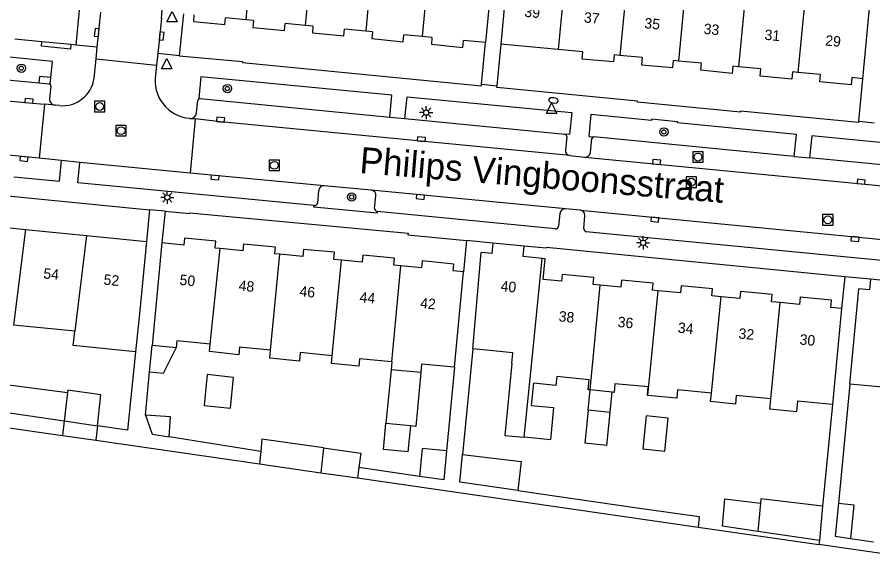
# Model space of a CAD drawing. Extents: x 132998 to 136004, y 396998 to 398512.
# Drawn here: x 133315.3 to 133397.2, y 397209.9 to 397262.2 of the extents above; entities that cross this region are included whole.
import ezdxf

# ---------------------------------------------------------------- set-up
doc = ezdxf.new("R2010")
doc.units = 0
for name, color, linetype in [('gg-afsc-erfafscheiding', 7, 'Continuous'), ('gg-anno-huisnummerreeks BGT', 7, 'Continuous'), ('gg-anno-openbare ruimte label', 7, 'Continuous'), ('gg-bbg-gedigitaliseerde bebouwing', 7, 'Continuous'), ('gg-bbg-gedigitaliseerde bijgebouw', 7, 'Continuous'), ('gg-bbg-hoofdgebouw', 7, 'Continuous'), ('gg-bbg-luifel en loopbrug', 7, 'Continuous'), ('gg-bbg-tussenscheiding', 7, 'Continuous'), ('gg-knt-verharding', 7, 'Continuous'), ('gg-knt-verharding nz', 7, 'Continuous'), ('gt-grn-weggrens', 7, 'Continuous'), ('gt-symb-boom', 7, 'Continuous'), ('gt-symb-brandkraan', 7, 'Continuous'), ('gt-symb-kolk', 7, 'Continuous'), ('gt-symb-lichtmast', 7, 'Continuous'), ('gt-symb-rioolschacht', 7, 'Continuous'), ('gt-symb-waterafsluiter', 7, 'Continuous')]:
    doc.layers.add(name, color=color, linetype=linetype)

# ---------------------------------------------------------------- blocks, each defined once
blk = doc.blocks.new('gt0-RS')
at = {"layer": 'gt-symb-rioolschacht'}
blk.add_lwpolyline([(-0.5, -0.5), (0.5, -0.5), (0.5, 0.5), (-0.5, 0.5)], close=True, dxfattribs=at)
blk.add_circle((0, 0), 0.375, dxfattribs=at)
blk = doc.blocks.new('gt0-KOLK')
at = {"layer": 'gt-symb-kolk'}
blk.add_lwpolyline([(0, 0), (0.375, 0), (0.375, 0.4), (-0.375, 0.4), (-0.375, 0), (0, 0)], dxfattribs=at)
blk = doc.blocks.new('gt0-LMAST')
at = {"layer": 'gt-symb-lichtmast'}
for p, q in [((-0.182, 0.173), (-0.447, 0.438)), ((-0.005, 0.246), (-0.005, 0.621)), ((0.172, 0.173), (0.437, 0.438)), ((-0.255, -0.004), (-0.63, -0.004)), ((-0.182, -0.181), (-0.447, -0.446)), ((-0.005, -0.254), (-0.005, -0.629)), ((0.437, -0.446), (0.172, -0.181)), ((0.245, -0.004), (0.62, -0.004))]:
    blk.add_line(p, q, dxfattribs=at)
blk.add_circle((-0.005, -0.004), 0.25, dxfattribs=at)
blk = doc.blocks.new('gt0-BOOM')
at = {"layer": 'gt-symb-boom'}
for radius in [0.4, 0.2]:
    blk.add_circle((0, 0), radius, dxfattribs=at)
blk = doc.blocks.new('gt0-WAFSL')
at = {"layer": 'gt-symb-waterafsluiter'}
for p, q in [((-0.5, -0.333), (0, 0.667)), ((0, 0.667), (0.5, -0.333)), ((0.5, -0.333), (-0.5, -0.333))]:
    blk.add_line(p, q, dxfattribs=at)
blk = doc.blocks.new('gt0-BR')
at = {"layer": 'gt-symb-brandkraan'}
for centre, radius, start, end in [((-0.244, 0), 0.206, 107.56694, 252.43307), ((0.599, -2.664), 3, 106.89205, 107.56694), ((0, -0.691), 0.938, 73.10799, 106.89205), ((-0.599, -2.664), 3, 72.43309, 73.10799), ((0.244, 0), 0.206, 287.56695, 72.43309), ((0.599, 2.664), 3, 252.43307, 253.10797), ((0, 0.691), 0.938, 253.10797, 286.89206), ((-0.599, 2.664), 3, 286.89206, 287.56695)]:
    blk.add_arc(centre, radius, start, end, dxfattribs=at)

msp = doc.modelspace()

# ---------------------------------------------------------------- linework, layer by layer
at = {"layer": 'gg-afsc-erfafscheiding'}
for p, q in [((133358.937, 397230.482), (133357.969, 397220.358)), ((133327.615, 397224.121), (133328.011, 397228.268)), ((133357.197, 397228.715), (133356.425, 397220.702)), ((133395.041, 397227.094), (133393.943, 397215.701)), ((133393.375, 397225.144), (133392.437, 397215.412)), ((133338.653, 397220.647), (133329.869, 397222.06)), ((133353.859, 397218.276), (133348.046, 397219.112)), ((133363.262, 397216.923), (133374.679, 397215.28)), ((133392.123, 397212.148), (133392.086, 397211.766)), ((133395.114, 397212.341), (133397.324, 397212.023))]:
    msp.add_line(p, q, dxfattribs=at)
for points in [[(133326.647, 397230.186), (133325.89, 397222.681), (133323.03, 397223.106)], [(133374.679, 397215.28), (133380.608, 397214.427), (133380.509, 397213.431)]]:
    msp.add_lwpolyline(points, dxfattribs=at)
at = {"layer": 'gg-bbg-gedigitaliseerde bebouwing'}
for p, q in [((133362.697, 397270.929), (133361.63, 397259.61)), ((133361.118, 397269.918), (133360.16, 397259.77)), ((133396.28, 397256.31), (133397.175, 397265.797)), ((133327.71, 397240.73), (133327.028, 397233.814)), ((133329.19, 397240.6), (133328.252, 397230.784)), ((133358.937, 397230.482), (133359.75, 397239.68)), ((133357.197, 397228.715), (133358.06, 397237.84)), ((133395.041, 397227.094), (133395.92, 397236.21)), ((133327.028, 397233.814), (133326.647, 397230.186)), ((133394.26, 397234.33), (133393.375, 397225.144)), ((133320.86, 397232.149), (133314.991, 397232.742)), ((133330.55, 397230.552), (133328.252, 397230.784)), ((133351.196, 397229.224), (133351.125, 397228.478)), ((133372.302, 397226.326), (133370.169, 397226.539))]:
    msp.add_line(p, q, dxfattribs=at)
for points in [[(133326.647, 397230.186), (133320.695, 397230.786), (133320.86, 397232.149)], [(133333.813, 397230.911), (133330.619, 397231.235), (133330.55, 397230.552)], [(133339.595, 397230.347), (133336.613, 397230.637), (133336.542, 397229.9), (133333.741, 397230.205), (133333.813, 397230.911)], [(133345.494, 397229.816), (133342.428, 397230.117), (133342.348, 397229.299), (133339.52, 397229.576), (133339.595, 397230.347)], [(133351.196, 397229.224), (133348.098, 397229.518), (133348.028, 397228.805), (133345.42, 397229.061), (133345.494, 397229.816)], [(133362.687, 397229.069), (133362.79, 397230.095), (133358.937, 397230.482)], [(133357.197, 397228.715), (133354.05, 397229.016), (133353.973, 397228.206)], [(133362.687, 397229.069), (133362.021, 397222.191), (133363.864, 397222.012)], [(133370.169, 397226.539), (133369.998, 397226.556), (133370.094, 397227.512), (133366.98, 397227.825), (133366.893, 397226.959), (133364.754, 397227.174)], [(133364.754, 397227.174), (133364.549, 397225.061), (133366.689, 397224.853), (133366.39, 397221.768), (133363.864, 397222.012)], [(133375.72, 397226.024), (133375.669, 397226.029), (133375.748, 397226.822), (133372.553, 397227.14), (133372.47, 397226.309), (133372.302, 397226.326)], [(133381.79, 397226.236), (133378.546, 397226.561), (133378.465, 397225.75), (133375.72, 397226.024)], [(133400.897, 397223.654), (133398.291, 397223.903), (133398.568, 397226.759), (133395.041, 397227.094)], [(133387.474, 397225.685), (133384.173, 397226.006), (133384.093, 397225.188), (133381.709, 397225.426), (133381.79, 397226.236)], [(133393.375, 397225.144), (133390.042, 397225.467), (133389.943, 397224.448), (133387.378, 397224.697), (133387.474, 397225.685)]]:
    msp.add_lwpolyline(points, dxfattribs=at)
at = {"layer": 'gg-bbg-gedigitaliseerde bijgebouw'}
for p, q in [((133351.125, 397228.478), (133350.635, 397223.318)), ((133353.973, 397228.206), (133353.483, 397223.046)), ((133314.29, 397227.045), (133320.153, 397226.308)), ((133313.971, 397224.453), (133319.823, 397223.583)), ((133369.991, 397224.597), (133369.676, 397221.447)), ((133372.108, 397224.385), (133369.991, 397224.597)), ((133371.793, 397221.235), (133372.108, 397224.385)), ((133319.823, 397223.583), (133323.03, 397223.106)), ((133352.968, 397223.095), (133350.635, 397223.318)), ((133353.483, 397223.046), (133352.968, 397223.095)), ((133371.793, 397221.235), (133369.676, 397221.447)), ((133338.653, 397220.647), (133338.538, 397219.469)), ((133348.046, 397219.112), (133347.904, 397218.122)), ((133392.437, 397215.412), (133392.123, 397212.148)), ((133392.123, 397212.148), (133386.23, 397213.016))]:
    msp.add_line(p, q, dxfattribs=at)
for points in [[(133333.215, 397225.044), (133335.751, 397224.786), (133336.052, 397227.744), (133333.516, 397228.002), (133333.215, 397225.044)], [(133323.03, 397223.106), (133323.328, 397226.061), (133320.178, 397226.521), (133320.153, 397226.308)], [(133327.615, 397224.121), (133328.256, 397222.319), (133329.869, 397222.06)], [(133329.869, 397222.06), (133329.993, 397223.968), (133327.615, 397224.121)], [(133375.225, 397220.912), (133377.342, 397220.7), (133377.657, 397223.847), (133375.54, 397224.059), (133375.225, 397220.912)], [(133344.639, 397220.996), (133338.767, 397221.825), (133338.653, 397220.647)], [(133344.639, 397220.996), (133348.244, 397220.487), (133348.046, 397219.112)], [(133356.425, 397220.702), (133354.115, 397220.929), (133353.859, 397218.276)], [(133356.425, 397220.702), (133356.159, 397217.945), (133353.859, 397218.276)], [(133363.262, 397216.923), (133357.717, 397217.721), (133357.969, 397220.358)], [(133357.969, 397220.358), (133363.59, 397219.693), (133363.262, 397216.923)], [(133386.23, 397213.016), (133382.839, 397213.516), (133383.088, 397216.126), (133386.487, 397215.708)], [(133392.437, 397215.412), (133386.528, 397216.139), (133386.487, 397215.708)]]:
    msp.add_lwpolyline(points, dxfattribs=at)
at = {"layer": 'gg-bbg-hoofdgebouw'}
for p, q in [((133337.209, 397261.953), (133335.284, 397262.136)), ((133337.966, 397261.881), (133337.209, 397261.953)), ((133342.905, 397261.411), (133340.985, 397261.594)), ((133343.634, 397261.342), (133342.905, 397261.411)), ((133348.696, 397260.86), (133346.66, 397261.054)), ((133349.339, 397260.799), (133348.696, 397260.86)), ((133317.692, 397259.844), (133315.096, 397260.104)), ((133354.086, 397260.348), (133352.355, 397260.512)), ((133355.034, 397260.258), (133354.086, 397260.348)), ((133320.461, 397259.567), (133317.692, 397259.844)), ((133320.93, 397259.52), (133320.461, 397259.567)), ((133360.16, 397259.77), (133358.059, 397259.97)), ((133367.133, 397259.086), (133361.63, 397259.61)), ((133369.471, 397258.863), (133367.133, 397259.086)), ((133373.03, 397258.524), (133372.48, 397258.576)), ((133375.147, 397258.322), (133373.03, 397258.524)), ((133378.628, 397257.991), (133378.152, 397258.036)), ((133380.851, 397257.779), (133378.628, 397257.991)), ((133384.375, 397257.444), (133383.846, 397257.494)), ((133386.519, 397257.24), (133384.375, 397257.444)), ((133390.074, 397256.901), (133389.569, 397256.949)), ((133392.222, 397256.696), (133390.074, 397256.901)), ((133396.28, 397256.31), (133395.236, 397256.409)), ((133309.86, 397242.53), (133316.117, 397241.899)), ((133316.117, 397241.899), (133321.969, 397241.309)), ((133321.969, 397241.309), (133327.71, 397240.73)), ((133331.295, 397240.399), (133329.19, 397240.6)), ((133363.88, 397240.3), (133360.85, 397240.59)), ((133334.747, 397240.069), (133334.297, 397240.112)), ((133336.967, 397239.857), (133334.747, 397240.069)), ((133340.487, 397239.52), (133339.973, 397239.569)), ((133342.661, 397239.312), (133340.487, 397239.52)), ((133346.39, 397238.956), (133345.658, 397239.026)), ((133348.346, 397238.769), (133346.39, 397238.956)), ((133352.07, 397238.413), (133351.381, 397238.479)), ((133354.043, 397238.224), (133352.07, 397238.413)), ((133358.06, 397237.84), (133357.063, 397237.935)), ((133400.05, 397236.83), (133397.03, 397237.12)), ((133371.141, 397236.57), (133370.463, 397236.636)), ((133373.129, 397236.377), (133371.141, 397236.57)), ((133376.689, 397236.032), (133376.16, 397236.083)), ((133378.834, 397235.824), (133376.689, 397236.032)), ((133382.712, 397235.449), (133381.843, 397235.533)), ((133384.521, 397235.274), (133382.712, 397235.449)), ((133388.369, 397234.901), (133387.538, 397234.981)), ((133390.209, 397234.723), (133388.369, 397234.901)), ((133394.26, 397234.33), (133393.223, 397234.43)), ((133309.13, 397223.7), (133319.654, 397222.186)), ((133319.654, 397222.186), (133322.863, 397221.724)), ((133322.863, 397221.724), (133338.538, 397219.469)), ((133347.904, 397218.122), (133380.509, 397213.431)), ((133380.509, 397213.431), (133392.086, 397211.766)), ((133405.018, 397209.906), (133392.086, 397211.766))]:
    msp.add_line(p, q, dxfattribs=at)
for points in [[(133321.977, 397271.051), (133321.602, 397267.585), (133321.709, 397267.57), (133320.93, 397259.52)], [(133332.252, 397262.425), (133332.195, 397261.764), (133335.224, 397261.503), (133335.284, 397262.136)], [(133337.966, 397261.881), (133337.903, 397261.216), (133340.922, 397260.928), (133340.985, 397261.594)], [(133343.634, 397261.342), (133343.591, 397260.682), (133346.598, 397260.398), (133346.66, 397261.054)], [(133349.339, 397260.799), (133349.288, 397260.137), (133352.29, 397259.843), (133352.355, 397260.512)], [(133355.034, 397260.258), (133354.98, 397259.596), (133357.993, 397259.3), (133358.059, 397259.97)], [(133372.48, 397258.576), (133372.403, 397257.916), (133369.41, 397258.19), (133369.471, 397258.863)], [(133375.147, 397258.322), (133375.084, 397257.648), (133378.088, 397257.368), (133378.152, 397258.036)], [(133383.846, 397257.494), (133383.781, 397256.819), (133380.787, 397257.108), (133380.851, 397257.779)], [(133389.569, 397256.949), (133389.504, 397256.266), (133386.454, 397256.556), (133386.519, 397257.24)], [(133395.236, 397256.409), (133395.169, 397255.725), (133392.157, 397256.018), (133392.222, 397256.696)], [(133334.297, 397240.112), (133334.353, 397240.765), (133331.363, 397241.069), (133331.295, 397240.399)], [(133336.967, 397239.857), (133337.03, 397240.516), (133340.036, 397240.228), (133339.973, 397239.569)], [(133360.85, 397240.59), (133360.76, 397239.59), (133359.75, 397239.68)], [(133345.658, 397239.026), (133345.72, 397239.702), (133342.725, 397239.978), (133342.661, 397239.312)], [(133365.585, 397239.119), (133363.78, 397239.3), (133363.88, 397240.3)], [(133351.381, 397238.479), (133351.442, 397239.137), (133348.408, 397239.418), (133348.346, 397238.769)], [(133357.063, 397237.935), (133357.125, 397238.582), (133354.105, 397238.873), (133354.043, 397238.224)], [(133367.444, 397236.928), (133365.67, 397237.1), (133365.87, 397239.09), (133365.585, 397239.119)], [(133370.463, 397236.636), (133370.525, 397237.296), (133367.508, 397237.589), (133367.444, 397236.928)], [(133397.03, 397237.12), (133396.94, 397236.11), (133395.92, 397236.21)], [(133376.16, 397236.083), (133376.223, 397236.748), (133373.197, 397237.049), (133373.129, 397236.377)], [(133381.843, 397235.533), (133381.909, 397236.22), (133378.9, 397236.506), (133378.834, 397235.824)], [(133387.538, 397234.981), (133387.603, 397235.679), (133384.587, 397235.957), (133384.521, 397235.274)], [(133393.223, 397234.43), (133393.286, 397235.129), (133390.275, 397235.4), (133390.209, 397234.723)]]:
    msp.add_lwpolyline(points, dxfattribs=at)
at = {"layer": 'gg-bbg-luifel en loopbrug'}
for p, q in [((133328.011, 397228.268), (133328.252, 397230.784)), ((133369.991, 397224.597), (133370.169, 397226.539)), ((133372.108, 397224.385), (133372.302, 397226.326)), ((133319.823, 397223.583), (133319.654, 397222.186)), ((133323.03, 397223.106), (133322.863, 397221.724))]:
    msp.add_line(p, q, dxfattribs=at)
for points in [[(133328.011, 397228.268), (133329.329, 397228.135), (133330.55, 397230.552)], [(133352.968, 397223.095), (133352.733, 397220.613), (133350.399, 397220.836), (133350.635, 397223.318)], [(133393.943, 397215.701), (133393.64, 397212.553), (133395.114, 397212.341)], [(133393.943, 397215.701), (133395.424, 397215.558), (133395.114, 397212.341)]]:
    msp.add_lwpolyline(points, dxfattribs=at)
at = {"layer": 'gg-bbg-tussenscheiding'}
for p, q in [((133338.124, 397271.325), (133337.209, 397261.953)), ((133349.6, 397270.272), (133348.696, 397260.86)), ((133354.994, 397269.853), (133354.086, 397260.348)), ((133368.037, 397268.508), (133367.133, 397259.086)), ((133373.937, 397268.005), (133373.03, 397258.524)), ((133379.603, 397268.157), (133378.628, 397257.991)), ((133385.272, 397266.812), (133384.375, 397257.444)), ((133390.973, 397266.307), (133390.074, 397256.901)), ((133316.117, 397241.899), (133314.991, 397232.742)), ((133321.969, 397241.309), (133320.86, 397232.149)), ((133333.813, 397230.911), (133334.747, 397240.069)), ((133339.595, 397230.347), (133340.487, 397239.52)), ((133345.494, 397229.816), (133346.39, 397238.956)), ((133364.555, 397228.881), (133365.585, 397239.119)), ((133351.196, 397229.224), (133352.07, 397238.413)), ((133370.169, 397226.539), (133371.141, 397236.57)), ((133375.72, 397226.024), (133376.689, 397236.032)), ((133381.79, 397226.236), (133382.712, 397235.449)), ((133387.474, 397225.685), (133388.369, 397234.901)), ((133363.864, 397222.012), (133364.555, 397228.881)), ((133353.973, 397228.206), (133351.125, 397228.478)), ((133320.153, 397226.308), (133319.823, 397223.583)), ((133344.639, 397220.996), (133344.412, 397218.624)), ((133338.538, 397219.469), (133344.412, 397218.624)), ((133344.412, 397218.624), (133347.904, 397218.122)), ((133386.487, 397215.708), (133386.23, 397213.016))]:
    msp.add_line(p, q, dxfattribs=at)
msp.add_lwpolyline([(133343.986, 397272.685), (133343.868, 397271.452), (133342.905, 397261.411)], dxfattribs=at)
at = {"layer": 'gg-knt-verharding'}
for p, q in [((133329.132, 397262.07), (133334.087, 397316.082)), ((133323.003, 397259.31), (133323.336, 397262.658)), ((133331.25, 397262.52), (133330.833, 397258.507)), ((133329.132, 397262.07), (133328.787, 397258.723)), ((133322.892, 397258.198), (133323.003, 397259.31)), ((133359.783, 397255.777), (133360.16, 397259.77)), ((133361.63, 397259.61), (133361.255, 397255.638)), ((133328.787, 397258.723), (133328.672, 397257.603)), ((133322.709, 397256.361), (133322.892, 397258.198)), ((133322.892, 397258.198), (133328.672, 397257.603)), ((133328.672, 397257.603), (133328.578, 397256.69)), ((133314.066, 397256.227), (133317.396, 397255.907)), ((133317.396, 397255.907), (133318.38, 397255.813)), ((133395.896, 397252.244), (133396.28, 397256.31)), ((133318.553, 397255.599), (133318.431, 397254.416)), ((133332.834, 397254.405), (133350.995, 397252.638)), ((133317.944, 397253.86), (133317.44, 397248.694)), ((133318.952, 397253.773), (133317.944, 397253.86)), ((133319.367, 397253.732), (133318.952, 397253.773)), ((133332.492, 397253.04), (133332.622, 397254.234)), ((133350.995, 397252.638), (133352.457, 397252.496)), ((133331.872, 397252.515), (133331.835, 397252.519)), ((133331.872, 397252.515), (133332.373, 397252.458)), ((133332.373, 397252.458), (133331.875, 397247.267)), ((133352.457, 397252.496), (133367.766, 397251.007)), ((133367.94, 397250.795), (133367.817, 397249.473)), ((133370.212, 397249.254), (133370.335, 397250.583)), ((133389.725, 397248.882), (133370.519, 397250.744)), ((133319.578, 397248.482), (133317.44, 397248.694)), ((133368.231, 397248.962), (133369.683, 397248.808)), ((133389.725, 397248.882), (133391.188, 397248.74)), ((133409.15, 397246.998), (133391.188, 397248.74)), ((133321.341, 397248.308), (133319.578, 397248.482)), ((133331.875, 397247.267), (133321.341, 397248.308)), ((133349.223, 397245.652), (133344.727, 397246.07)), ((133310.15, 397245.512), (133328.006, 397243.779)), ((133344.192, 397245.626), (133344.074, 397244.415)), ((133349.546, 397243.908), (133349.672, 397245.114)), ((133328.006, 397243.779), (133327.71, 397240.73)), ((133329.485, 397243.635), (133329.19, 397240.6)), ((133369.243, 397243.726), (133367.834, 397243.865)), ((133366.846, 397241.946), (133349.804, 397243.598)), ((133367.29, 397243.423), (133367.161, 397242.212)), ((133358.351, 397240.833), (133358.06, 397237.84)), ((133365.982, 397240.098), (133363.88, 397240.3)), ((133394.55, 397237.358), (133394.26, 397234.33))]:
    msp.add_line(p, q, dxfattribs=at)
for points in [[(133320.461, 397259.567), (133320.419, 397259.143), (133317.649, 397259.419), (133317.692, 397259.844)], [(133318.557, 397256.424), (133318.704, 397257.961), (133314.275, 397258.407), (133314.066, 397256.227)], [(133330.833, 397258.507), (133336.911, 397257.951), (133336.899, 397257.849), (133359.768, 397255.624), (133359.783, 397255.777)], [(133318.557, 397256.424), (133317.456, 397256.529), (133317.396, 397255.907)], [(133318.38, 397255.813), (133318.497, 397255.802), (133318.557, 397256.424)], [(133350.995, 397252.638), (133351.199, 397254.735), (133332.925, 397256.501), (133332.722, 397254.416), (133332.834, 397254.405)], [(133395.896, 397252.244), (133395.884, 397252.124), (133384.585, 397253.213), (133384.576, 397253.119), (133374.7, 397254.067), (133374.71, 397254.17), (133361.24, 397255.481), (133361.255, 397255.638)], [(133352.457, 397252.496), (133352.66, 397254.584), (133368.414, 397253.066), (133368.209, 397250.964), (133367.766, 397251.007)], [(133389.725, 397248.882), (133389.928, 397250.97), (133378.535, 397252.082), (133378.547, 397252.195), (133376.063, 397252.45), (133376.05, 397252.324), (133370.261, 397252.868), (133370.059, 397250.789), (133370.519, 397250.744)], [(133409.15, 397246.998), (133409.353, 397249.09), (133391.391, 397250.838), (133391.188, 397248.74)], [(133315.023, 397246.928), (133319.388, 397246.508), (133319.578, 397248.482)], [(133343.758, 397244.165), (133321.147, 397246.339), (133321.341, 397248.308)], [(133329.485, 397243.635), (133331.821, 397243.408), (133331.828, 397243.474), (133352.751, 397241.523), (133352.737, 397241.378), (133358.351, 397240.833)], [(133349.804, 397243.598), (133349.79, 397243.454), (133343.745, 397244.034), (133343.758, 397244.165)], [(133369.562, 397241.981), (133369.682, 397243.19), (133369.627, 397243.458), (133369.558, 397243.564), (133369.418, 397243.662), (133369.243, 397243.726)], [(133441.155, 397234.453), (133430.662, 397235.779), (133369.813, 397241.67)], [(133394.55, 397237.358), (133365.989, 397240.17), (133365.982, 397240.098)]]:
    msp.add_lwpolyline(points, dxfattribs=at)
for centre, radius, start, end in [((133319.662, 397256.795), 3.077, 264.49211, 351.88894), ((133332.131, 397256.107), 3.6, 170.68449, 265.28578), ((133318.348, 397255.61), 0.205, 356.91134, 80.99358), ((133319.013, 397254.355), 0.585, 174.01581, 264.01743), ((133332.834, 397254.188), 0.217, 90.04116, 167.7384), ((133331.919, 397253.089), 0.575, 265.35354, 355.16059), ((133367.739, 397250.807), 0.201, 356.46264, 82.29256), ((133370.516, 397250.562), 0.182, 89.01934, 173.35251), ((133368.289, 397249.432), 0.474, 175.09198, 262.93515), ((133369.711, 397249.312), 0.504, 266.83523, 353.43326), ((133344.683, 397245.578), 0.493, 84.90791, 174.47109), ((133349.172, 397245.153), 0.502, 355.54394, 84.15095), ((133343.79, 397244.45), 0.287, 263.67087, 353.02694), ((133349.866, 397243.912), 0.32, 180.74609, 258.7923), ((133367.788, 397243.366), 0.501, 84.72741, 173.46031), ((133366.884, 397242.22), 0.277, 262.02233, 358.33614), ((133369.885, 397241.985), 0.323, 180.7529, 257.05929)]:
    msp.add_arc(centre, radius, start, end, dxfattribs=at)
at = {"layer": 'gg-knt-verharding nz'}
for p, q in [((133317.44, 397248.694), (133314.463, 397248.995)), ((133369.683, 397248.808), (133430.462, 397242.922)), ((133344.727, 397246.07), (133331.875, 397247.267)), ((133367.834, 397243.865), (133349.223, 397245.652))]:
    msp.add_line(p, q, dxfattribs=at)
for points in [[(133282.037, 397257.264), (133286.043, 397256.862), (133316.442, 397253.991), (133317.944, 397253.86)], [(133368.231, 397248.962), (133334.785, 397252.188), (133332.373, 397252.458)], [(133369.243, 397243.726), (133395.558, 397241.177), (133415.959, 397239.181), (133430.673, 397237.773), (133435.029, 397237.253), (133436.821, 397237.014)]]:
    msp.add_lwpolyline(points, dxfattribs=at)
at = {"layer": 'gt-grn-weggrens'}
for p, q in [((133323.003, 397259.31), (133320.93, 397259.52)), ((133330.833, 397258.507), (133328.787, 397258.723)), ((133359.783, 397255.777), (133361.255, 397255.638)), ((133395.896, 397252.244), (133397.378, 397252.099)), ((133329.485, 397243.635), (133328.006, 397243.779)), ((133360.85, 397240.59), (133358.351, 397240.833)), ((133397.03, 397237.12), (133394.55, 397237.358))]:
    msp.add_line(p, q, dxfattribs=at)

# ---------------------------------------------------------------- block references
at = {"layer": 'gt-symb-boom'}
for p in [(133315.732, 397257.313), (133335.453, 397255.365), (133377.238, 397251.223), (133347.348, 397244.997)]:
    msp.add_blockref('gt0-BOOM', p, dxfattribs=at)
at = {"layer": 'gt-symb-brandkraan', "rotation": 171.54573827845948}
msp.add_blockref('gt0-BR', (133366.674, 397254.237), dxfattribs=at)
at = {"layer": 'gt-symb-kolk'}
for p, rotation in [((133323.142, 397260.709), 84.3094813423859), ((133328.96, 397260.403), -95.87680238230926), ((133316.442, 397253.991), -4.977430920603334), ((133334.785, 397252.188), -5.52831746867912), ((133354.002, 397250.327), -5.47934933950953), ((133315.997, 397248.831), 173.92805581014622), ((133376.525, 397248.145), -5.520285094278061), ((133334.284, 397247.052), 174.90127949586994), ((133396.11, 397246.253), -5.560444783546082), ((133353.941, 397245.203), 174.56081561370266), ((133376.397, 397243.033), 174.47168253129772), ((133395.558, 397241.177), 174.47168253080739)]:
    msp.add_blockref('gt0-KOLK', p, dxfattribs=dict(at, rotation=rotation))
at = {"layer": 'gt-symb-lichtmast'}
for p in [(133354.488, 397253.069), (133329.707, 397244.957), (133375.258, 397240.615)]:
    msp.add_blockref('gt0-LMAST', p, dxfattribs=at)
at = {"layer": 'gt-symb-rioolschacht'}
for p in [(133323.222, 397253.646), (133325.277, 397251.34), (133339.939, 397248.026), (133380.512, 397248.81), (133379.876, 397246.411), (133392.938, 397242.811)]:
    msp.add_blockref('gt0-RS', p, dxfattribs=at)
at = {"layer": 'gt-symb-waterafsluiter'}
for p in [(133330.152, 397262.077), (133329.645, 397257.571), (133366.495, 397253.321)]:
    msp.add_blockref('gt0-WAFSL', p, dxfattribs=at)

# ---------------------------------------------------------------- texts
at = {"layer": 'gg-anno-huisnummerreeks BGT'}
for s, rotation, p in [('39', 354.5, (133363.858, 397262.237)), ('37', 354.8, (133369.553, 397261.691)), ('35', 354.7, (133375.341, 397261.139)), ('33', 354.5, (133381.015, 397260.601)), ('31', 354.6, (133386.843, 397260.034)), ('29', 354.4, (133392.653, 397259.487)), ('54', 354.3, (133317.8, 397237.206)), ('52', 354.3, (133323.565, 397236.625)), ('50', 354.2, (133330.841, 397236.6)), ('48', 354.5, (133336.495, 397236.046)), ('46', 354.7, (133342.322, 397235.497)), ('40', 354.5, (133361.578, 397235.999)), ('44', 354.7, (133348.075, 397234.93)), ('42', 354.5, (133353.874, 397234.374)), ('38', 354.4, (133367.136, 397233.104)), ('36', 354.3, (133372.786, 397232.567)), ('34', 354.6, (133378.544, 397232.019)), ('32', 354.7, (133384.354, 397231.46)), ('30', 354.8, (133390.199, 397230.889))]:
    msp.add_text(s, height=1, rotation=rotation, dxfattribs=at).set_placement(p)
at = {"layer": 'gg-anno-openbare ruimte label'}
msp.add_text('Philips Vingboonsstraat', height=2.5, rotation=355.3, dxfattribs=at).set_placement((133348.053, 397247.294))

doc.saveas('drawing.dxf')
